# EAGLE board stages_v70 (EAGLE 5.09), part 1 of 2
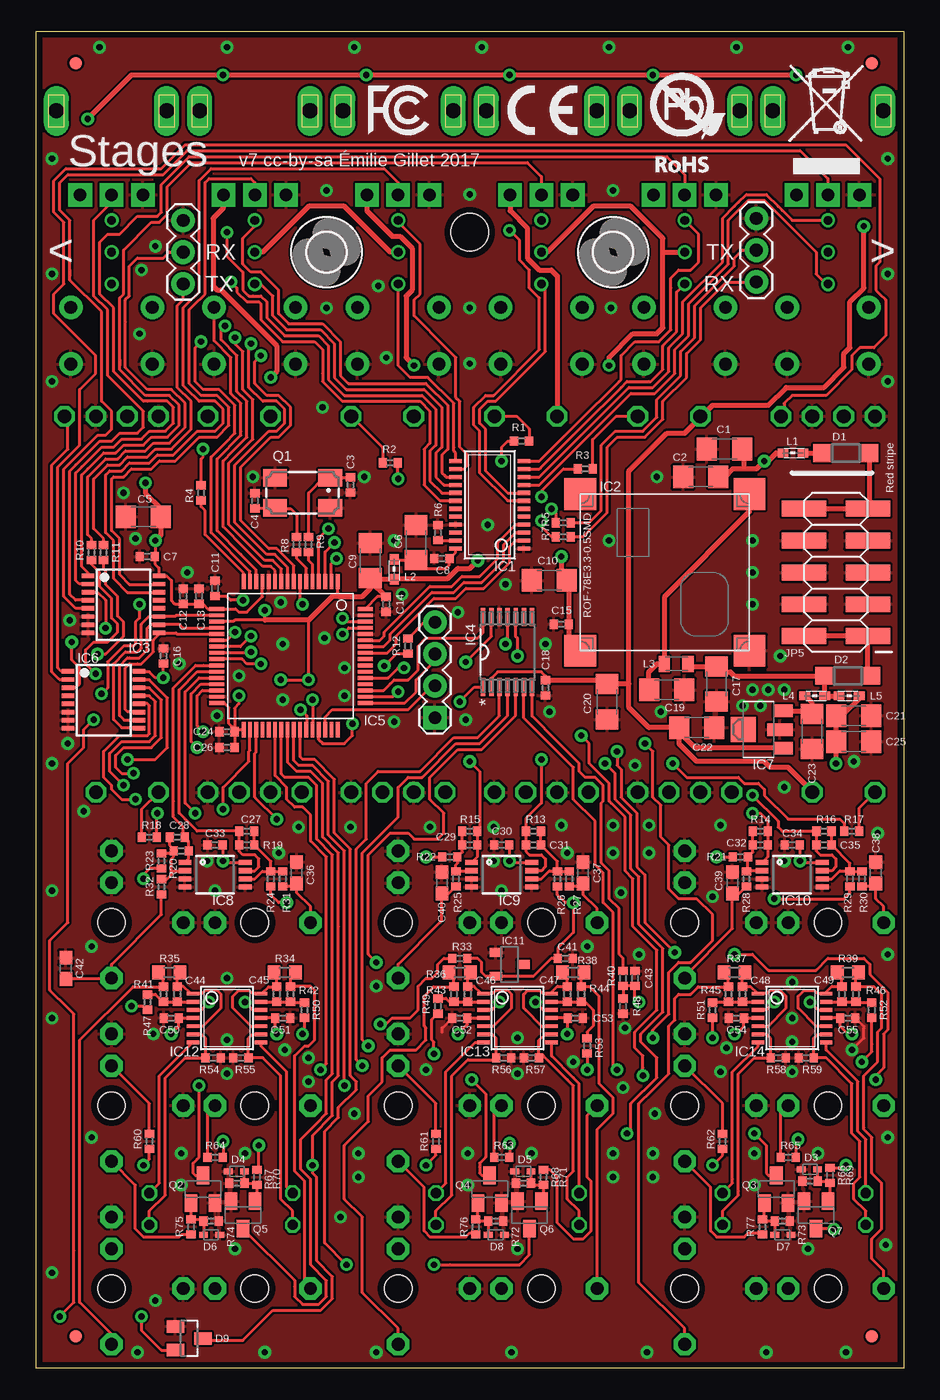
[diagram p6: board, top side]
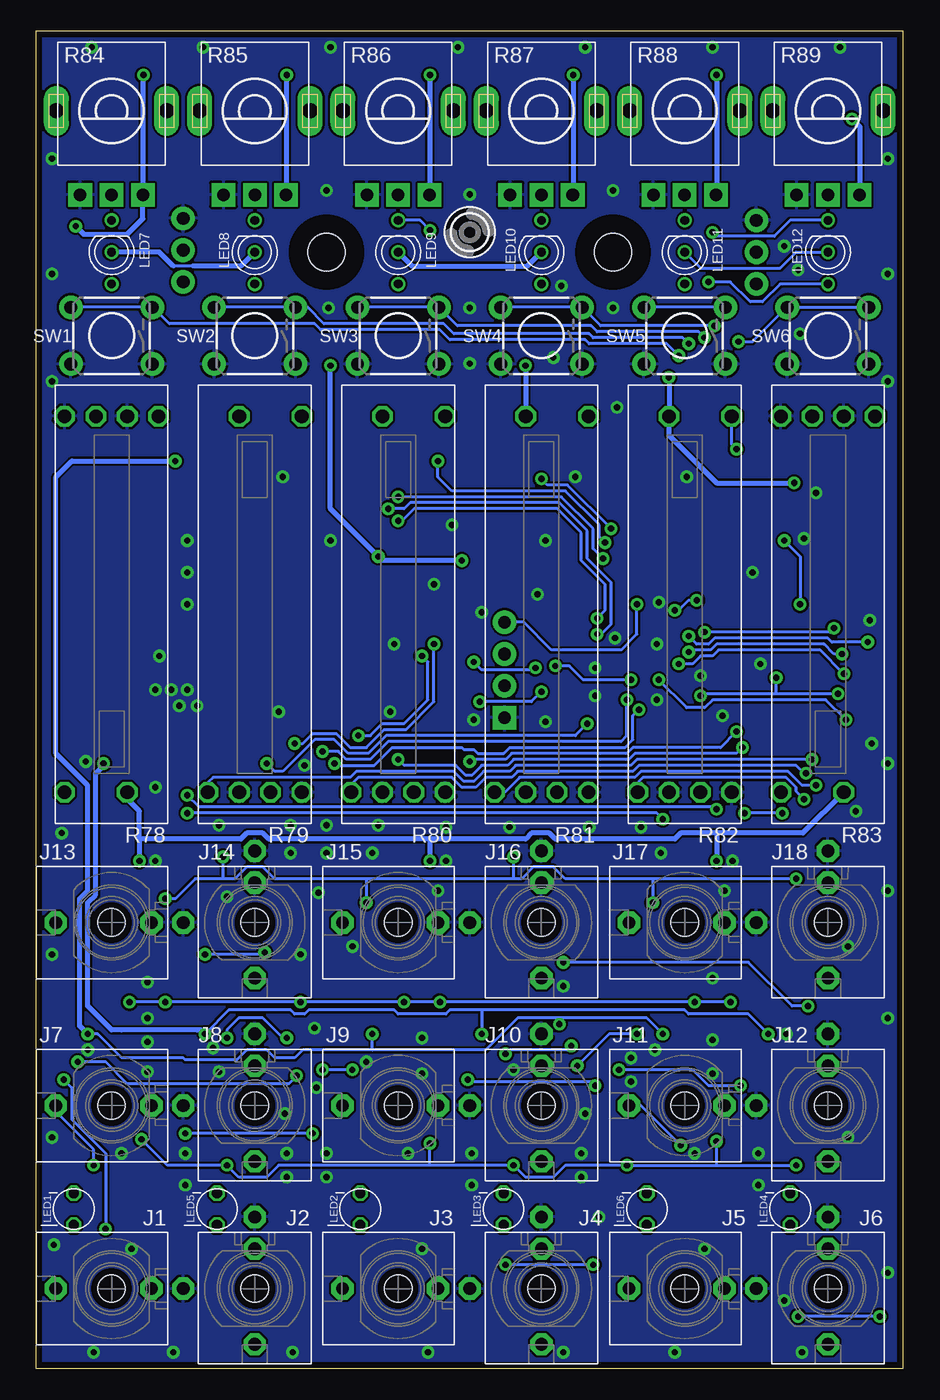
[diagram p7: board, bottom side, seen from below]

Size 69.2 x 106.68 mm. Coordinates in mm from the lower left corner, seen from the top.
Outline: 69.2,0 0,0 0,106.68 69.2,106.68 69.2,0
Copper layers (1*16): Top 0.035mm / dielectric 1.5mm / Bottom 0.035mm
Design rules "PCBCart-Standard": minimum track width 8mil, minimum drill 0.4mm, track to track 7mil, track to pad 7mil, pad to pad 7mil, via to via 7mil, smd to smd 7mil, copper to edge 20mil, drill to drill 8mil, minimum pad ring 8mil, minimum via ring 10mil, stop-mask expansion 3mil, vias tented up to drill 25mil, thermal gap 8mil

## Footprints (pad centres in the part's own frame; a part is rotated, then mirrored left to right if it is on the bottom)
C1206 = smd 1.6 x 1.8: 1 -1.4,0; 2 1.4,0
C0402 = smd 0.65 x 0.75: 1 -0.6,0; 2 0.6,0
C0603 = smd 1.1 x 1: 1 -0.85,0; 2 0.85,0
SOD123 = smd 1.4 x 1.4: A 1.9,0; C -1.9,0
SOD523 = smd 0.7 x 0.5: A 0.7,0; C -0.6,0
SOT23 = smd 1 x 1.4: 1 -0.95,-1.1; 2 0.95,-1.1; 3 0,1.1
3,0 = hole 3: 0,0
3,0TINY = hole 3: 0,0
TSSOP24_0635 = smd 0.33 x 1: 1 -3.493,-2.725; 2 -2.857,-2.725; 3 -2.223,-2.725; 4 -1.587,-2.725; 5 -0.953,-2.725; 6 -0.318,-2.725; 7 0.318,-2.725; 8 0.953,-2.725; 9 1.587,-2.725; 10 2.223,-2.725; 11 2.857,-2.725; 12 3.493,-2.725; 13 3.493,2.725; 14 2.857,2.725; 15 2.223,2.725; 16 1.587,2.725; 17 0.953,2.725; 18 0.318,2.725; 19 -0.318,2.725; 20 -0.953,2.725; 21 -1.587,2.725; 22 -2.223,2.725; 23 -2.857,2.725; 24 -3.493,2.725
ROF78EXX-0.5SMD = smd 2.54 x 2.54: 1 -6.25,6.75; 2 6.25,6.75; 3 6.25,-6.75; 4 -6.25,-6.75
TSSOP16_065 = smd 0.35 x 1: 1 -1.95,-2.825; 2 -1.3,-2.825; 3 -0.65,-2.825; 4 0,-2.825; 5 0.65,-2.825; 6 1.3,-2.825; 7 1.95,-2.825; 8 2.6,-2.825; 9 2.6,2.825; 10 1.95,2.825; 11 1.3,2.825; 12 0.65,2.825; 13 0,2.825; 14 -0.65,2.825; 15 -1.3,2.825; 16 -1.95,2.825
RPDSOG14 = smd 1.422 x 0.356: 1 -2.8,1.95; 2 -2.8,1.3; 3 -2.8,0.65; 4 -2.8,0; 5 -2.8,-0.65; 6 -2.8,-1.3; 7 -2.8,-1.95; 8 2.8,-1.95; 9 2.8,-1.3; 10 2.8,-0.65; 11 2.8,0; 12 2.8,0.65; 13 2.8,1.3; 14 2.8,1.95
TQFP-10X10-64 = smd 1.2 x 0.3: 1 -5.936,3.75; 2 -5.936,3.25; 3 -5.936,2.75; 4 -5.936,2.25; 5 -5.936,1.75; 6 -5.936,1.25; 7 -5.936,0.75; 8 -5.936,0.25; 9 -5.936,-0.25; 10 -5.936,-0.75; 11 -5.936,-1.25; 12 -5.936,-1.75; 13 -5.936,-2.25; 14 -5.936,-2.75; 15 -5.936,-3.25; 16 -5.936,-3.75; 33 5.886,-3.75; 34 5.886,-3.25; 35 5.886,-2.75; 36 5.886,-2.25; 37 5.886,-1.75; 38 5.886,-1.25; 39 5.886,-0.75; 40 5.886,-0.25; 41 5.886,0.25; 42 5.886,0.75; 43 5.886,1.25; 44 5.886,1.75; 45 5.886,2.25; 46 5.886,2.75; 47 5.886,3.25; 48 5.886,3.75 | smd 0.3 x 1.2: 17 -3.75,-5.911; 18 -3.25,-5.911; 19 -2.75,-5.911; 20 -2.25,-5.911; 21 -1.75,-5.911; 22 -1.25,-5.911; 23 -0.75,-5.911; 24 -0.25,-5.911; 25 0.25,-5.911; 26 0.75,-5.911; 27 1.25,-5.911; 28 1.75,-5.911; 29 2.25,-5.911; 30 2.75,-5.911; 31 3.25,-5.911; 32 3.75,-5.911; 49 3.75,5.936; 50 3.25,5.936; 51 2.75,5.936; 52 2.25,5.936; 53 1.75,5.936; 54 1.25,5.936; 55 0.75,5.936; 56 0.25,5.936; 57 -0.25,5.936; 58 -0.75,5.936; 59 -1.25,5.936; 60 -1.75,5.936; 61 -2.25,5.936; 62 -2.75,5.936; 63 -3.25,5.936; 64 -3.75,5.936
SOT89 = smd 1 x 1.5: 1 -1.499,-1.981; 3 1.499,-1.981 | smd 1 x 2: 2 0,-1.727 | smd 2 x 2: 2@1 0,1.194
MSOP-8 = smd 0.41 x 1.02: 1 -0.975,-2.4; 2 -0.325,-2.4; 3 0.325,-2.4; 4 0.975,-2.4; 5 0.975,2.4; 6 0.325,2.4; 7 -0.325,2.4; 8 -0.975,2.4
DBZ_R-PDSO-G3 = smd 0.7 x 1: 1 -0.95,-1.1; 2 0.95,-1.1; 3 0,1.1
TSSOP14_065 = smd 0.305 x 0.991: 1 -1.95,-2.718; 2 -1.3,-2.718; 3 -0.65,-2.718; 4 0,-2.718; 5 0.65,-2.718; 6 1.3,-2.718; 7 1.95,-2.718; 8 1.95,2.718; 9 1.3,2.718; 10 0.65,2.718; 11 0,2.718; 12 -0.65,2.718; 13 -1.3,2.718; 14 -1.95,2.718
WQP_PJ_301M6 = drill 1.016 pad 1.778 octagon: P1 0,-5.715; P2 0,-3.175; P3 0,4.445 | hole 2.2: 0,0
FIDUCIAL-1X2 = smd 1 x 1: 1 0,0
1X03 = drill 1.016 pad 1.88 round: 1 0,0; 2 2.54,0; 3 5.08,0
2X5-SMD = smd 3.556 x 1.27: 1 -2.54,5.08; 2 2.54,5.08; 3 -2.54,2.54; 4 2.54,2.54; 5 -2.54,0; 6 2.54,0; 7 -2.54,-2.54; 8 2.54,-2.54; 9 -2.54,-5.08; 10 2.54,-5.08
1X04 = drill 1.016 pad 1.88 square: 1 0,0 | drill 1.016 pad 1.88 round: 2 2.54,0; 3 5.08,0; 4 7.62,0
0603 = smd 0.85 x 0.7: 1 -0.9,0; 2 0.7,0
L2012C = smd 0.9 x 1.25: 1 -0.9,0; 2 1,0
LED3MM = drill 0.813 octagon: 1 -1.27,0; 2 1.27,0
LED-BICOLOR-THROUGHHOLE-LUMEX = drill 0.7 round: A 0,0; GREEN_C 2.54,0; RED_C -2.54,0
CTS406 = smd 1.9 x 1.4: 1 -2.2,-1.2; 2 2.2,-1.2; 3 2.2,1.2; 4 -2.2,1.2
SOT23-BEC = smd 1 x 1.4: B -0.95,-1.1; C 0,1.1; E 0.95,-1.1
R0402 = smd 0.65 x 0.75: 1 -0.6,0; 2 0.6,0
R0603 = smd 1 x 1.1: 1 -0.85,0; 2 0.85,0
BOURNS_SLIDER = drill 1.1 octagon: 1 -15,1.25; 2 -15,3.75; 3 15,1.25; B 15,-3.75; DUMMY -15,-1.25; E -15,-3.75
ALPS_POT_NARROW = drill 1 pad 1.88 square: P$1 -2.5,6.7; P$2 0,6.7; P$3 2.5,6.7 | drill 1.2 pad 2 long: P$4 -4.4,0; P$5 4.4,0
TACTILE-PTH = drill 1.016 pad 1.88 round: 1 -3.251,2.261; 2 3.251,2.261; 3 -3.251,-2.261; 4 3.251,-2.261

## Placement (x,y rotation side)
C1  22u  [C1206]  54.91,73.34 0 top
C2  22u  [C1206]  53,71.12 0 top
C3  20p  [C0402]  25.06,70.48 90 top
C4  20p  [C0402]  17.44,69.21 270 top
C5  22u  [C1206]  8.55,67.94 180 top
C6  22u  [C1206]  30.3,65.88 90 top
C7  100n  [C0402]  8.87,64.77 180 top
C8  100n  [C0402]  32.36,64.61 180 top
C9  22u  [C1206]  26.65,64.45 90 top
C10  22u  [C1206]  40.94,62.87 180 top
C11  100n  [C0402]  14.27,62.23 90 top
C12  1u  [C0402]  11.73,61.59 90 top
C13  100n  [C0402]  13,61.59 90 top
C14  100n  [C0402]  27.92,60.96 270 top
C15  100n  [C0402]  41.89,59.37 180 top
C16  100n  [C0402]  10.14,56.83 90 top
C17  22u  [C1206]  54.27,54.61 270 top
C18  1u  [C0402]  40.62,54.29 270 top
C19  22u  [C1206]  50.3,54.13 0 top
C20  22u  [C1206]  45.54,53.18 270 top
C21  22u  [C1206]  65.23,52.07 0 top
C22  22u  [C1206]  52.68,51.12 0 top
C23  22u  [C1206]  61.89,50.8 270 top
C24  100n  [C0402]  15.22,50.8 180 top
C25  22u  [C1206]  65.23,50.01 0 top
C26  1u  [C0402]  15.22,49.53 180 top
C27  2.2n  [C0402]  16.81,42.86 180 top
C28  470p  [C0402]  11.25,42.39 0 top
C29  2.2n  [C0402]  34.59,41.75 0 top
C30  100n  [C0402]  37.13,41.75 180 top
C31  2.2n  [C0402]  39.67,41.75 180 top
C32  2.2n  [C0402]  57.76,41.75 0 top
C33  100n  [C0402]  14.27,41.75 180 top
C34  100n  [C0402]  60.3,41.75 180 top
C35  2.2n  [C0402]  62.84,41.75 180 top
C36  ESD  [C0603]  20.78,39.53 90 top
C37  ESD  [C0603]  43.64,39.53 90 top
C38  ESD  [C0603]  66.97,39.53 90 top
C39  ESD  [C0603]  55.54,38.74 90 top
C40  ESD  [C0603]  32.37,38.73 90 top
C41  1u  [C0402]  42.21,32.7 0 top
C42  ESD  [C0603]  2.36,31.91 90 top
C43  1u  [C0402]  47.76,31.11 90 top
C44  100p  [C0402]  11.25,29.84 90 top
C45  100p  [C0402]  19.19,29.84 90 top
C46  100p  [C0402]  34.43,29.84 90 top
C47  100p  [C0402]  42.37,29.84 90 top
C48  100p  [C0402]  56.34,29.84 90 top
C49  100p  [C0402]  64.27,29.84 90 top
C50  100n  [C0402]  10.77,27.94 180 top
C51  100n  [C0402]  19.66,27.94 180 top
C52  100n  [C0402]  33.79,27.94 180 top
C53  100n  [C0402]  43,27.94 180 top
C54  100n  [C0402]  55.86,27.94 180 top
C55  100n  [C0402]  64.75,27.94 180 top
D1  1N5819HW  [SOD123]  64.59,73.03 180 top
D2  1N5819HW  [SOD123]  64.75,55.24 0 top
D3  1N4148  [SOD523]  61.73,15.88 180 top
D4  1N4148  [SOD523]  16.01,15.72 180 top
D5  1N4148  [SOD523]  38.87,15.72 180 top
D6  1N4148  [SOD523]  13.95,10.64 0 top
D7  1N4148  [SOD523]  59.51,10.64 0 top
D8  1N4148  [SOD523]  36.65,10.64 0 top
D9  BAT54S  [SOT23]  12.2,2.38 270 top
H1  MOUNT-HOLE3.0  [3,0]  46.02,89.06 0 top
H2  MOUNT-HOLE3.0  [3,0]  23.16,89.06 0 top
H3  MOUNT-HOLE3.0TINY  [3,0TINY]  34.59,90.65 0 bottom
IC1  TLC59281DBQ  [TSSOP24_0635]  36.17,68.9 90 top
IC2  ROF-78E3.3-0.5SMD  [ROF78EXX-0.5SMD]  50.14,63.5 270 top
IC3  4051PW  [TSSOP16_065]  6.97,61.28 270 top
IC4  DAC8168IAPW  [RPDSOG14]  37.6,57.15 90 top
IC5  STM32F373RBT6  [TQFP-10X10-64]  20.3,56.83 270 top
IC6  4051PW  [TSSOP16_065]  5.38,53.66 270 top
IC7  LD2981ABU33  [SOT89]  57.61,50.96 90 top
IC8  MCP6002  [MSOP-8]  14.27,39.37 270 top
IC9  MCP6002  [MSOP-8]  37.13,39.37 270 top
IC10  MCP6002  [MSOP-8]  60.3,39.37 270 top
IC11  LM4040B25  [DBZ_R-PDSO-G3]  37.76,32.23 270 top
IC12  TL074PW  [TSSOP14_065]  15.22,27.94 270 top
IC13  TL074PW  [TSSOP14_065]  38.4,27.94 270 top
IC14  TL074PW  [TSSOP14_065]  60.3,27.94 270 top
J1  PJ301_THONKICONN6  [WQP_PJ_301M6]  63.16,6.35 90 bottom
J2  PJ301_THONKICONN6  [WQP_PJ_301M6]  51.73,6.35 180 bottom
J3  PJ301_THONKICONN6  [WQP_PJ_301M6]  40.3,6.35 90 bottom
J4  PJ301_THONKICONN6  [WQP_PJ_301M6]  28.87,6.35 180 bottom
J5  PJ301_THONKICONN6  [WQP_PJ_301M6]  17.44,6.35 90 bottom
J6  PJ301_THONKICONN6  [WQP_PJ_301M6]  6.01,6.35 180 bottom
J7  PJ301_THONKICONN6  [WQP_PJ_301M6]  63.16,20.95 90 bottom
J8  PJ301_THONKICONN6  [WQP_PJ_301M6]  51.73,20.95 180 bottom
J9  PJ301_THONKICONN6  [WQP_PJ_301M6]  40.3,20.95 90 bottom
J10  PJ301_THONKICONN6  [WQP_PJ_301M6]  28.87,20.95 180 bottom
J11  PJ301_THONKICONN6  [WQP_PJ_301M6]  17.44,20.95 90 bottom
J12  PJ301_THONKICONN6  [WQP_PJ_301M6]  6.01,20.95 180 bottom
J13  PJ301_THONKICONN6  [WQP_PJ_301M6]  63.16,35.56 90 bottom
J14  PJ301_THONKICONN6  [WQP_PJ_301M6]  51.73,35.56 180 bottom
J15  PJ301_THONKICONN6  [WQP_PJ_301M6]  40.3,35.56 90 bottom
J16  PJ301_THONKICONN6  [WQP_PJ_301M6]  28.87,35.56 180 bottom
J17  PJ301_THONKICONN6  [WQP_PJ_301M6]  17.44,35.56 90 bottom
J18  PJ301_THONKICONN6  [WQP_PJ_301M6]  6.01,35.56 180 bottom
JP1  FIDUCIAL1X2  [FIDUCIAL-1X2]  3.15,104.14 0 top
JP2  FIDUCIAL1X2  [FIDUCIAL-1X2]  66.66,104.14 0 top
JP3  [1X03]  57.45,91.76 270 top
JP4  [1X03]  11.73,91.6 270 top
JP5  M05X2SMD  [2X5-SMD]  63.8,63.5 180 top
JP6  [1X04]  31.81,51.91 90 top
JP7  FIDUCIAL1X2  [FIDUCIAL-1X2]  3.15,2.54 0 top
JP8  FIDUCIAL1X2  [FIDUCIAL-1X2]  66.66,2.54 0 top
L1  [0603]  60.46,73.03 0 top
L2  [0603]  28.56,63.66 270 top
L3  33u  [L2012C]  51.1,56.2 180 top
L4  [0603]  62.21,53.66 0 top
L5  [0603]  64.75,53.66 180 top
LED1  WP937EGW  [LED3MM]  66.18,12.7 270 bottom
LED2  WP937EGW  [LED3MM]  43.32,12.7 270 bottom
LED3  WP937EGW  [LED3MM]  31.89,12.7 270 bottom
LED4  WP937EGW  [LED3MM]  9.03,12.7 270 bottom
LED5  WP937EGW  [LED3MM]  54.75,12.7 270 bottom
LED6  WP937EGW  [LED3MM]  20.46,12.7 270 bottom
LED7  SSL-LX3059IGW-CA  [LED-BICOLOR-THROUGHHOLE-LUMEX]  63.16,89.06 270 bottom
LED8  SSL-LX3059IGW-CA  [LED-BICOLOR-THROUGHHOLE-LUMEX]  51.73,89.06 270 bottom
LED9  SSL-LX3059IGW-CA  [LED-BICOLOR-THROUGHHOLE-LUMEX]  40.3,89.06 270 bottom
LED10  SSL-LX3059IGW-CA  [LED-BICOLOR-THROUGHHOLE-LUMEX]  28.87,89.06 270 bottom
LED11  SSL-LX3059IGW-CA  [LED-BICOLOR-THROUGHHOLE-LUMEX]  17.44,89.06 270 bottom
LED12  SSL-LX3059IGW-CA  [LED-BICOLOR-THROUGHHOLE-LUMEX]  6.01,89.06 270 bottom
Q1  8MHz  [CTS406]  21.25,69.85 180 top
Q2  MMBT3904  [SOT23-BEC]  13.32,14.29 0 top
Q3  MMBT3904  [SOT23-BEC]  59.03,14.29 0 top
Q4  MMBT3904  [SOT23-BEC]  36.18,14.29 0 top
Q5  MMBT3904  [SOT23-BEC]  16.49,12.22 180 top
Q6  MMBT3904  [SOT23-BEC]  39.35,12.22 180 top
Q7  MMBT3904  [SOT23-BEC]  62.21,12.22 180 top
R1  15k  [R0402]  38.71,73.98 180 top
R2  15k  [R0402]  28.24,72.23 0 top
R3  15k  [R0402]  43.8,71.75 180 top
R4  15k  [R0402]  13.16,69.85 270 top
R5  100  [R0402]  42.05,67.47 0 top
R6  10k  [R0402]  32.05,66.68 90 top
R7  100  [R0402]  42.05,66.36 0 top
R8  100  [R0402]  20.78,65.72 90 top
R9  100  [R0402]  21.73,65.72 90 top
R10  100  [R0402]  4.43,65.09 90 top
R11  100  [R0402]  5.38,65.09 90 top
R12  10k  [R0402]  29.67,57.63 270 top
R13  20k  [R0402]  39.67,42.86 0 top
R14  20k  [R0402]  57.76,42.86 180 top
R15  20k  [R0402]  34.59,42.86 180 top
R16  20k  [R0402]  62.84,42.86 0 top
R17  15k  [R0402]  65.07,42.86 180 top
R18  15k  [R0402]  9.03,42.39 0 top
R19  20k  [R0402]  16.81,41.75 0 top
R20  20k  [R0402]  11.57,41.27 180 top
R21  30k  [R0402]  56.18,40.8 180 top
R22  30k  [R0402]  33,40.8 180 top
R23  30k  [R0402]  9.98,40.48 270 top
R24  30k  [R0402]  18.71,39.05 270 top
R25  100k  [R0402]  33.48,39.05 270 top
R26  30k  [R0402]  41.57,39.05 270 top
R27  100k  [R0402]  42.53,39.05 270 top
R28  100k  [R0402]  56.65,39.05 270 top
R29  30k  [R0402]  64.91,39.05 270 top
R30  100k  [R0402]  65.86,39.05 270 top
R31  100k  [R0402]  19.66,39.05 270 top
R32  100k  [R0402]  9.98,38.42 270 top
R33  10k  [R0402]  33.79,32.7 0 top
R34  1.0k  [R0603]  19.82,31.59 180 top
R35  1.0k  [R0603]  10.62,31.59 0 top
R36  1.0k  [R0603]  33.79,31.59 0 top
R37  1.0k  [R0603]  55.7,31.59 0 top
R38  1.0k  [R0603]  42.84,31.59 180 top
R39  1.0k  [R0603]  64.75,31.59 180 top
R40  130k  [R0402]  46.81,31.11 90 top
R41  130k  [R0402]  10.14,29.84 270 top
R42  130k  [R0402]  20.3,29.84 270 top
R43  130k  [R0402]  33.32,29.84 270 top
R44  130k  [R0402]  43.48,29.84 270 top
R45  130k  [R0402]  55.22,29.84 270 top
R46  130k  [R0402]  65.39,29.84 270 top
R47  20k  [R0402]  8.87,29.21 270 top
R48  100k  [R0402]  46.81,28.89 90 top
R49  20k  [R0402]  32.05,28.89 270 top
R50  20k  [R0402]  21.41,28.57 270 top
R51  20k  [R0402]  53.95,28.57 270 top
R52  20k  [R0402]  66.66,28.57 270 top
R53  20k  [R0402]  43.95,25.72 270 top
R54  1.0k  [R0402]  14.11,24.77 0 top
R55  1.0k  [R0402]  16.33,24.77 180 top
R56  1.0k  [R0402]  37.29,24.77 0 top
R57  1.0k  [R0402]  39.51,24.77 180 top
R58  1.0k  [R0402]  59.19,24.77 0 top
R59  1.0k  [R0402]  61.42,24.77 180 top
R60  10k  [R0402]  9.03,18.1 90 top
R61  10k  [R0402]  31.89,18.1 90 top
R62  10k  [R0402]  54.75,18.1 90 top
R63  10k  [R0402]  37.13,16.83 180 top
R64  10k  [R0402]  14.27,16.83 180 top
R65  10k  [R0402]  59.99,16.83 180 top
R66  100k  [R0402]  63.32,15.4 270 top
R67  100k  [R0402]  17.6,15.24 270 top
R68  100k  [R0402]  40.46,15.24 270 top
R69  100k  [R0402]  61.73,14.92 0 top
R70  100k  [R0402]  16.01,14.76 0 top
R71  100k  [R0402]  38.87,14.76 0 top
R72  100k  [R0402]  36.65,11.75 180 top
R73  100k  [R0402]  59.51,11.75 180 top
R74  100k  [R0402]  13.95,11.75 180 top
R75  100k  [R0402]  12.36,11.27 90 top
R76  100k  [R0402]  35.06,11.27 90 top
R77  100k  [R0402]  57.92,11.27 90 top
R78  20kB  [BOURNS_SLIDER]  63.16,60.96 270 bottom
R79  20kB  [BOURNS_SLIDER]  51.73,60.96 90 bottom
R80  20kB  [BOURNS_SLIDER]  40.3,60.96 90 bottom
R81  20kB  [BOURNS_SLIDER]  28.87,60.96 90 bottom
R82  20kB  [BOURNS_SLIDER]  17.44,60.96 90 bottom
R83  20kB  [BOURNS_SLIDER]  6.01,60.96 270 bottom
R84  10kB  [ALPS_POT_NARROW]  63.16,100.33 180 bottom
R85  10kB  [ALPS_POT_NARROW]  51.73,100.33 180 bottom
R86  10kB  [ALPS_POT_NARROW]  40.3,100.33 180 bottom
R87  10kB  [ALPS_POT_NARROW]  28.87,100.33 180 bottom
R88  10kB  [ALPS_POT_NARROW]  17.44,100.33 180 bottom
R89  10kB  [ALPS_POT_NARROW]  6.01,100.33 180 bottom
SW1  [TACTILE-PTH]  63.16,82.39 180 bottom
SW2  [TACTILE-PTH]  51.73,82.39 180 bottom
SW3  [TACTILE-PTH]  40.3,82.39 180 bottom
SW4  [TACTILE-PTH]  28.87,82.39 180 bottom
SW5  [TACTILE-PTH]  17.44,82.39 180 bottom
SW6  [TACTILE-PTH]  6.01,82.39 180 bottom
U$1  [ROHS]  48.88,95.25 0 top
U$2  [ROHS_2]  59.99,95.25 0 top
U$3  [FCC_SMALL]  26.49,98.42 0 top
U$4  [CE_SMALL]  37.6,98.42 0 top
